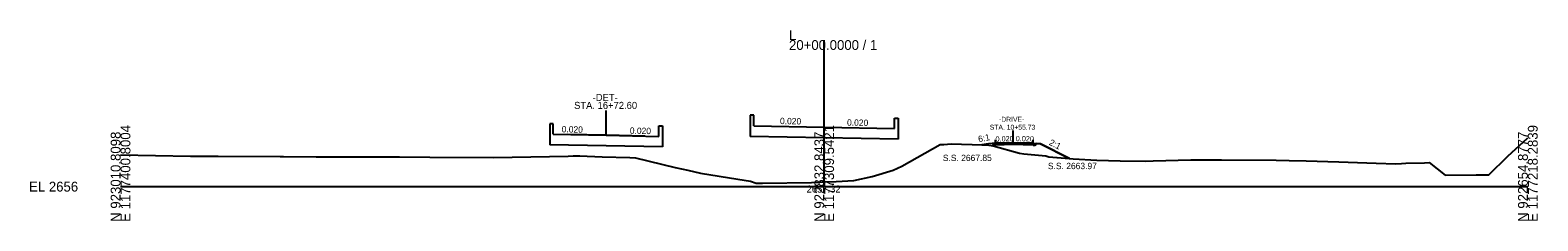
# Model space of a CAD drawing. Extents: x -26 to 1403, y -10 to 9563.
# Drawn here: x 974.3 to 1402.8, y -9.7 to 44.4 of the extents above; entities that cross this region are included whole.
import ezdxf

# ---------------------------------------------------------------- set-up
doc = ezdxf.new("R2010")
doc.units = 0
for name, color, linetype in [('Exist Cross Section Cell', 7, 'Continuous'), ('Exist XS Center Line Elevation Label', 7, 'Continuous'), ('Exist XS Ground Line', 7, 'Continuous'), ('Prop XS Bridge', 7, 'Continuous'), ('Prop XS Ditch Slope Text', 7, 'Continuous'), ('Prop XS Dump Level', 7, 'Continuous'), ('Prop XS Earthwork Shape', 7, 'Continuous'), ('Prop XS EOT Tick Mark', 7, 'Continuous'), ('Prop XS Finish Grade', 7, 'Continuous'), ('Prop XS Finish Grade Earthwork', 7, 'Continuous'), ('Prop XS Finish Grade Pavement', 7, 'Continuous'), ('Prop XS Pvmt Edge Slope', 7, 'Continuous'), ('Prop XS SE Text', 7, 'Continuous'), ('Prop XS Side Slope Text', 7, 'Continuous'), ('Prop XS SS Elevation Text', 7, 'Continuous'), ('Prop XS Subgrade Earthwork', 7, 'Continuous'), ('Prop XS Vertical Lines', 7, 'Continuous'), ('Prop XS Vertical Lines Alignments', 7, 'Continuous')]:
    doc.layers.add(name, color=color, linetype=linetype)

msp = doc.modelspace()

# ---------------------------------------------------------------- linework, layer by layer
at = {"layer": 'Exist Cross Section Cell'}
for p, q in [((1200, 0), (1200, 41.58)), ((1000, 0), (1200, 0)), ((1200, 0), (1400, 0))]:
    msp.add_line(p, q, dxfattribs=at)
at = {"layer": 'Exist XS Ground Line'}
for p, q in [((1394.31, 8.64), (1399.89, 13.78)), ((1399.89, 13.78), (1400, 13.86)), ((1000, 8.98), (1019.85, 8.61)), ((1019.85, 8.61), (1027.72, 8.67)), ((1027.72, 8.67), (1045.38, 8.56)), ((1045.38, 8.56), (1046.27, 8.57)), ((1046.27, 8.57), (1055.57, 8.47)), ((1105.98, 8.3), (1127.25, 8.62)), ((1127.25, 8.62), (1128.63, 8.7)), ((1128.63, 8.7), (1130.54, 8.78)), ((1130.54, 8.78), (1136.93, 8.44)), ((1222.05, 5.79), (1232.93, 11.95)), ((1232.93, 11.95), (1234.05, 12)), ((1234.05, 12), (1236.05, 12.12)), ((1236.05, 12.12), (1245.01, 11.84)), ((1245.01, 11.84), (1246.82, 11.78)), ((1246.82, 11.78), (1248.02, 11.59)), ((1248.02, 11.59), (1255.55, 9.51)), ((1255.55, 9.51), (1256.77, 9.35)), ((1256.77, 9.35), (1263.01, 8.74)), ((1263.01, 8.74), (1263.87, 8.48)), ((1388.88, 3.32), (1394.31, 8.64)), ((1055.57, 8.47), (1078.65, 8.41)), ((1078.65, 8.41), (1079.24, 8.41)), ((1079.24, 8.41), (1087.88, 8.36)), ((1087.88, 8.36), (1105.98, 8.3)), ((1136.93, 8.44), (1144.74, 8.25)), ((1144.74, 8.25), (1146.37, 8.17)), ((1146.37, 8.17), (1157.68, 5.41)), ((1157.68, 5.41), (1161.28, 4.66)), ((1161.28, 4.66), (1164.8, 3.86)), ((1213.64, 2.89), (1219.59, 4.66)), ((1219.59, 4.66), (1222.05, 5.79)), ((1263.87, 8.48), (1270.72, 7.89)), ((1270.72, 7.89), (1277.52, 7.55)), ((1277.52, 7.55), (1284.08, 7.34)), ((1284.08, 7.34), (1291.29, 7.25)), ((1291.29, 7.25), (1293.51, 7.31)), ((1293.51, 7.31), (1304.18, 7.57)), ((1304.18, 7.57), (1308.86, 7.6)), ((1308.86, 7.6), (1312.95, 7.58)), ((1312.95, 7.58), (1328.49, 7.5)), ((1328.49, 7.5), (1332.19, 7.45)), ((1332.19, 7.45), (1337, 7.34)), ((1337, 7.34), (1346.24, 7.05)), ((1346.24, 7.05), (1356.91, 6.66)), ((1356.91, 6.66), (1362.44, 6.49)), ((1362.44, 6.49), (1364.08, 6.55)), ((1364.08, 6.55), (1365.31, 6.64)), ((1365.31, 6.64), (1370.64, 6.77)), ((1370.64, 6.77), (1371.99, 6.82)), ((1371.99, 6.82), (1376.48, 3.26)), ((1164.8, 3.86), (1175.43, 2.1)), ((1175.43, 2.1), (1179.06, 1.57)), ((1179.06, 1.57), (1180.68, 0.96)), ((1180.68, 0.96), (1182.46, 1.01)), ((1182.46, 1.01), (1196.4, 1.14)), ((1196.4, 1.14), (1200, 1.32)), ((1200, 1.32), (1203.36, 1.48)), ((1203.36, 1.48), (1208.42, 1.7)), ((1208.42, 1.7), (1213.64, 2.89)), ((1376.48, 3.26), (1385.33, 3.31)), ((1385.33, 3.31), (1388.88, 3.32))]:
    msp.add_line(p, q, dxfattribs=at)
at = {"layer": 'Prop XS Bridge'}
for p, q in [((1122, 17.86), (1122, 14.86)), ((1123, 17.86), (1122, 17.86)), ((1123, 14.86), (1123, 17.86)), ((1153, 14.26), (1153, 17.26)), ((1153, 17.26), (1154, 17.26)), ((1154, 17.26), (1154, 14.26)), ((1179, 20.24), (1179, 17.24)), ((1180, 20.24), (1179, 20.24)), ((1179, 17.24), (1179, 14.24)), ((1180, 17.24), (1180, 20.24)), ((1180, 17.25), (1200, 16.85)), ((1220, 19.46), (1221, 19.46)), ((1220, 16.45), (1220, 19.45)), ((1221, 19.46), (1221, 16.46)), ((1122, 14.86), (1122, 11.86)), ((1123, 14.86), (1138, 14.56)), ((1138, 14.56), (1153, 14.26)), ((1154, 14.26), (1154, 11.27)), ((1221, 13.46), (1179, 14.24)), ((1200, 16.85), (1220, 16.45)), ((1221, 16.46), (1221, 13.46)), ((1154, 11.27), (1122, 11.86))]:
    msp.add_line(p, q, dxfattribs=at)
at = {"layer": 'Prop XS Dump Level'}
for p, q in [((1138, 14.56), (1127, 14.78)), ((1149, 14.34), (1138, 14.56)), ((1253.72, 12.41), (1248.69, 12.31)), ((1253.72, 12.41), (1248.69, 12.31)), ((1259.42, 12.3), (1253.72, 12.41)), ((1259.42, 12.3), (1253.72, 12.41))]:
    msp.add_line(p, q, dxfattribs=at)
at = {"layer": 'Prop XS Earthwork Shape'}
msp.add_lwpolyline([(1244.84, 11.85), (1245.01, 11.84), (1246.82, 11.78), (1248.02, 11.59), (1255.55, 9.51), (1256.77, 9.35), (1263.01, 8.74), (1263.87, 8.48), (1269.76, 7.97), (1261.44, 12.14), (1260.37, 12.22), (1259.93, 11.79), (1259.42, 11.8), (1253.72, 11.91), (1248.69, 11.81), (1248.17, 11.8), (1247.74, 12.24), (1246.67, 12.15)], close=True, dxfattribs=at)
at = {"layer": 'Prop XS EOT Tick Mark'}
for p, q in [((1248.69, 12.31), (1248.69, 13.31)), ((1259.42, 12.3), (1259.42, 13.3))]:
    msp.add_line(p, q, dxfattribs=at)
at = {"layer": 'Prop XS Finish Grade'}
for p, q in [((1248.69, 12.31), (1247.74, 12.24)), ((1259.42, 12.3), (1260.37, 12.22))]:
    msp.add_line(p, q, dxfattribs=at)
at = {"layer": 'Prop XS Finish Grade Earthwork'}
for p, q in [((1246.67, 12.15), (1244.84, 11.85)), ((1247.74, 12.24), (1246.67, 12.15)), ((1260.37, 12.22), (1261.44, 12.14)), ((1261.44, 12.14), (1269.76, 7.97))]:
    msp.add_line(p, q, dxfattribs=at)
at = {"layer": 'Prop XS Finish Grade Pavement'}
for p, q in [((1248.69, 12.31), (1253.72, 12.41)), ((1253.72, 12.41), (1259.42, 12.3))]:
    msp.add_line(p, q, dxfattribs=at)
at = {"layer": 'Prop XS Pvmt Edge Slope'}
for p, q in [((1248.69, 12.31), (1248.17, 11.8)), ((1259.42, 12.3), (1259.93, 11.79))]:
    msp.add_line(p, q, dxfattribs=at)
at = {"layer": 'Prop XS Subgrade Earthwork'}
for p, q in [((1248.17, 11.8), (1247.74, 12.24)), ((1248.69, 11.81), (1248.17, 11.8)), ((1253.72, 11.91), (1248.69, 11.81)), ((1259.42, 11.8), (1253.72, 11.91)), ((1259.42, 11.8), (1259.93, 11.79)), ((1259.93, 11.79), (1260.37, 12.22))]:
    msp.add_line(p, q, dxfattribs=at)
at = {"layer": 'Prop XS Vertical Lines'}
for p, q in [((1138, 14.56), (1138, 21.56)), ((1253.72, 12.41), (1253.72, 15.91))]:
    msp.add_line(p, q, dxfattribs=at)

# ---------------------------------------------------------------- texts
at = {"layer": 'Exist Cross Section Cell'}
for s, p in [('L', (1190, 41.58)), ('20+00.0000 / 1', (1190, 38.78)), ('EL 2656', (974, -1.4))]:
    msp.add_text(s, height=2.8, dxfattribs=at).set_placement(p)
for s, p in [('E 1177400.8004', (1002.8, -10)), ('E 1177309.5421', (1202.8, -10)), ('E 1177218.2839', (1402.8, -10)), ('N 923010.8098', (1000, -10)), ('N 922832.8437', (1200, -10)), ('N 922654.8777', (1400, -10))]:
    msp.add_text(s, height=2.8, rotation=90, dxfattribs=at).set_placement(p)
at = {"layer": 'Exist XS Center Line Elevation Label'}
msp.add_text('2657.32', height=2, dxfattribs=at).set_placement((1195, -1.68))
at = {"layer": 'Prop XS Ditch Slope Text'}
msp.add_text('6:1', height=1.8, rotation=11.0172, dxfattribs=at).set_placement((1243.93, 12.58))
at = {"layer": 'Prop XS Dump Level'}
msp.add_text('Case1', height=0.04, dxfattribs=at).set_placement((1246.67, 12.11))
at = {"layer": 'Prop XS SE Text'}
for height, rotation, p in [(1.8, 358.8542, (1125.37, 15.4)), (1.8, 358.8542, (1187.42, 17.75)), (1.8, 358.8542, (1206.48, 17.32)), (1.8, 358.8542, (1144.74, 15.01)), (1.5, 1.1184, (1248.7, 12.77)), (1.5, 358.8331, (1254.43, 12.9))]:
    msp.add_text('0.020', height=height, rotation=rotation, dxfattribs=at).set_placement(p)
at = {"layer": 'Prop XS Side Slope Text'}
msp.add_text('2:1', height=1.8, rotation=333.7212, dxfattribs=at).set_placement((1263.75, 11.94))
at = {"layer": 'Prop XS SS Elevation Text'}
for s, p in [('S.S. 2667.85', (1233.72, 7.25)), ('S.S. 2663.97', (1263.58, 4.96))]:
    msp.add_text(s, height=1.8, dxfattribs=at).set_placement(p)
at = {"layer": 'Prop XS Vertical Lines'}
for s, p in [('-DET-', (1134.19, 24.3)), ('STA. 16+72.60', (1128.91, 22.05))]:
    msp.add_text(s, height=2, dxfattribs=at).set_placement(p)
at = {"layer": 'Prop XS Vertical Lines Alignments'}
for s, p in [('STA. 10+55.73', (1247.05, 16.16)), ('-DRIVE-', (1249.69, 18.41))]:
    msp.add_text(s, height=1.4, dxfattribs=at).set_placement(p)

doc.saveas('drawing.dxf')
